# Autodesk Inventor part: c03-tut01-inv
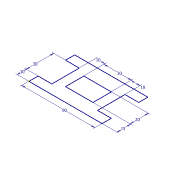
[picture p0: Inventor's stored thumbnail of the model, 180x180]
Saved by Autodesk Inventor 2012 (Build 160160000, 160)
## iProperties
Created: 2010-01
Part Number: c03-tut01-inv
Document SubType Name: Modeling
Designer: CADSoft
Density: 1 g/cm^3
Material: Default
Author: CADSoft
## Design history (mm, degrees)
sketch "Sketch1"
  geometry: L1 (80, 0)-(0, 0); L2 (0, 0)-(0, 10); L3 (0, 10)-(15, 10); L4 (15, 10)-(15, 40); L5 (15, 40)-(0, 40); L6 (0, 40)-(0, 50); L7 (0, 50)-(80, 50); L8 (80, 50)-(80, 40); L9 (80, 40)-(65, 40); L10 (65, 40)-(65, 10); L11 (65, 10)-(80, 10); L12 (80, 10)-(80, 0); L13 (25, 35)-(55, 35); L14 (55, 35)-(55, 15); L15 (55, 15)-(25, 15); L16 (25, 15)-(25, 35); 2 further points
  constraints: 32 end point, 9 equal length, 7 horizontal, 6 vertical, 2 coincident, 1 other
  dimensions: "d1" = 80 distance of L1.start L1.end; "d2" = 10 distance of L1.end L2.end; "d3" = 30 distance of L3.end L4.end; "d4" = 20 distance of L13.end L14.end; "d5" = 30 distance of L13.start L13.end; "d6" = 10 distance between parallel lines of L16 L4; "d7" = 10 distance between parallel lines of L10 L14; "d8" = 15 distance between parallel lines of L15 L1
